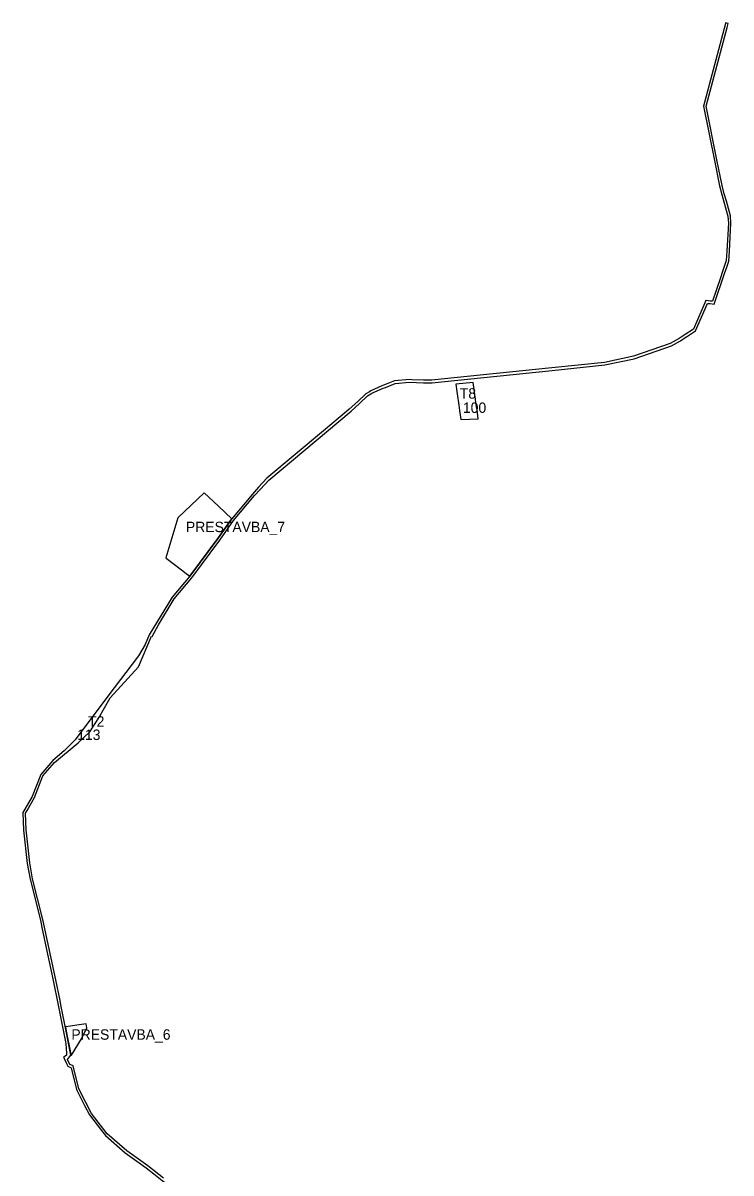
# Model space of a CAD drawing. Extents: x -477001 to -465642, y -1158278 to -1150672.
# Drawn here: x -473383 to -472568, y -1152921 to -1151597 of the extents above; entities that cross this region are included whole.
import ezdxf

# ---------------------------------------------------------------- set-up
doc = ezdxf.new("R2010")
doc.units = 0
for name, color, linetype in [('prestavba_n', 7, 'Continuous'), ('VPS_id', 7, 'Continuous'), ('VPS_n', 7, 'Continuous'), ('vyvlastneni_n', 7, 'Continuous')]:
    doc.layers.add(name, color=color, linetype=linetype)

msp = doc.modelspace()

# ---------------------------------------------------------------- linework, layer by layer
at = {"layer": 'prestavba_n'}
for p, q in [((-473174.2, -1152138.1), (-473204.5, -1152166.9)), ((-473157.8, -1152153.7), (-473174.2, -1152138.1)), ((-473142.5, -1152168.2), (-473157.8, -1152153.7)), ((-473204.5, -1152166.9), (-473218.5, -1152213)), ((-473142.7, -1152168.4), (-473142.5, -1152168.2)), ((-473218.5, -1152213), (-473218, -1152213.4)), ((-473218, -1152213.4), (-473198.9, -1152228.1)), ((-473198.9, -1152228.1), (-473196.5, -1152230)), ((-473196.5, -1152230), (-473190.8, -1152234.3)), ((-473190.8, -1152234.3), (-473190.8, -1152234.3)), ((-473328.1, -1152752.4), (-473334, -1152753.3)), ((-473320.9, -1152751.3), (-473328.1, -1152752.4)), ((-473327.1, -1152785.7), (-473315.4, -1152766.9)), ((-473327.6, -1152786), (-473327.1, -1152785.7))]:
    msp.add_line(p, q, dxfattribs=at)
for points in [[(-473190.8, -1152234.3), (-473158.4, -1152191), (-473142.7, -1152168.4)], [(-473315.4, -1152766.9), (-473309.3, -1152754.5), (-473310.2, -1152749.7), (-473320.9, -1152751.3)], [(-473334, -1152753.3), (-473333.1, -1152758.2), (-473328.2, -1152782.7)], [(-473328.2, -1152782.7), (-473327.6, -1152785.9), (-473327.6, -1152786)]]:
    msp.add_lwpolyline(points, dxfattribs=at)
at = {"layer": 'VPS_n'}
for p, q in [((-472570.1, -1151871.4), (-472569.6, -1151860.1)), ((-472611, -1151949.6), (-472620.5, -1151956)), ((-472618.8, -1151958.6), (-472608.6, -1151951.6)), ((-472984, -1152021.8), (-472987.9, -1152024.2)), ((-472864.4, -1152011.3), (-472884.3, -1152013.1)), ((-472884.3, -1152013.1), (-472883.2, -1152021.4)), ((-472883.2, -1152021.4), (-472882.8, -1152024.3)), ((-472861.8, -1152030.3), (-472864.4, -1152011.3)), ((-472997.3, -1152033), (-473007.1, -1152041.9)), ((-472987.9, -1152024.2), (-472997.3, -1152033)), ((-472882.8, -1152024.3), (-472881, -1152037.3)), ((-472861.3, -1152034.1), (-472861.8, -1152030.3)), ((-472860.5, -1152039.4), (-472861.3, -1152034.1)), ((-473010.4, -1152044.6), (-473036.8, -1152066.7)), ((-473007.1, -1152041.9), (-473010.4, -1152044.6)), ((-472881, -1152037.3), (-472880.1, -1152043.5)), ((-472880.1, -1152043.5), (-472878.7, -1152053.8)), ((-472860.1, -1152042.6), (-472860.5, -1152039.4)), ((-472858.7, -1152053), (-472860.1, -1152042.6)), ((-472878.7, -1152053.8), (-472858.7, -1152053)), ((-473036.8, -1152066.7), (-473101.9, -1152121.3)), ((-473226.7, -1152290.4), (-473208.7, -1152260.3)), ((-473234.1, -1152303.8), (-473226.7, -1152290.4)), ((-473242.1, -1152312.9), (-473249.8, -1152325.8)), ((-473234.8, -1152303.3), (-473234.1, -1152303.8)), ((-473345.1, -1152699.2), (-473359.8, -1152629.6)), ((-473354.5, -1152669.5), (-473350.8, -1152687.1)), ((-473340.1, -1152722.9), (-473345.1, -1152699.2)), ((-473342.1, -1152728.3), (-473333.7, -1152770.6)), ((-473335.4, -1152789.6), (-473332.7, -1152795.2)), ((-473325.6, -1152797.8), (-473328.7, -1152796.4)), ((-473327.5, -1152800.3), (-473327.1, -1152802)), ((-473292.3, -1152872.6), (-473287.9, -1152878.3)), ((-473287.9, -1152878.3), (-473265.1, -1152898.3)), ((-473265.1, -1152898.3), (-473240.9, -1152915.6))]:
    msp.add_line(p, q, dxfattribs=at)
for points in [[(-472596.2, -1151693.1), (-472572.2, -1151602.6), (-472571, -1151598), (-472573.9, -1151597.2), (-472574.1, -1151597.9), (-472599.3, -1151693), (-472586.8, -1151755.4)], [(-472583.9, -1151754.8), (-472583.9, -1151754.8), (-472596.2, -1151693.1)], [(-472586.8, -1151755.4), (-472580.8, -1151784.8), (-472578.3, -1151794.6), (-472575.8, -1151803.2), (-472571.3, -1151819.8), (-472570.7, -1151827.9), (-472572.5, -1151859.9), (-472573.1, -1151870.9)], [(-472569.6, -1151860.1), (-472567.7, -1151827.9), (-472568.4, -1151819.3), (-472572.9, -1151802.4), (-472575.4, -1151793.8), (-472577.8, -1151784.2), (-472583.9, -1151754.8)], [(-472573.1, -1151870.9), (-472577.3, -1151883.3), (-472579.9, -1151890.7), (-472589.1, -1151917.7), (-472591.5, -1151917.4), (-472594.1, -1151917.1), (-472596.3, -1151916.9), (-472596.8, -1151916.8), (-472611, -1151949.6)], [(-472608.6, -1151951.6), (-472594.9, -1151920.1), (-472594.1, -1151920.1), (-472591.5, -1151920.4), (-472587.1, -1151920.9), (-472574.6, -1151884.5), (-472572.9, -1151879.6), (-472570.1, -1151871.4)], [(-472620.5, -1151956), (-472627.4, -1151960.7), (-472637.6, -1151966.4)], [(-472637.6, -1151966.4), (-472680, -1151980.9), (-472713.3, -1151988), (-472774.1, -1151994.2)], [(-472773.7, -1151997.2), (-472712.8, -1151991), (-472679.2, -1151983.8), (-472636.3, -1151969.1)], [(-472636.3, -1151969.1), (-472625.9, -1151963.3), (-472619.2, -1151958.8), (-472618.8, -1151958.6)], [(-472774.1, -1151994.2), (-472901.3, -1152007.4), (-472912, -1152008.4), (-472913.7, -1152008.4), (-472921.6, -1152008.6), (-472935.2, -1152008), (-472937.8, -1152007.9), (-472955.2, -1152009.3), (-472964.7, -1152013.2), (-472967.7, -1152014.4), (-472969.5, -1152015.2), (-472982.5, -1152020.8), (-472984, -1152021.8)], [(-473005.1, -1152044.1), (-472995.3, -1152035.2), (-472986.1, -1152026.6), (-472982.4, -1152024.3), (-472981.1, -1152023.5), (-472968.3, -1152017.9), (-472966.5, -1152017.2), (-472963.6, -1152016), (-472954.5, -1152012.2), (-472937.7, -1152010.9), (-472921.7, -1152011.6), (-472913.6, -1152011.4), (-472911.9, -1152011.4), (-472901, -1152010.4), (-472773.7, -1151997.2)], [(-473140.4, -1152170.2), (-473116.1, -1152141.5), (-473109.4, -1152133.9), (-473099.8, -1152123.5), (-473005.1, -1152044.1)], [(-473101.9, -1152121.3), (-473111.7, -1152131.9), (-473118.4, -1152139.6), (-473142.7, -1152168.4)], [(-473142.7, -1152168.4), (-473158.4, -1152191), (-473190.8, -1152234.3), (-473211.1, -1152258.5), (-473237.4, -1152301.9), (-473242.1, -1152312.9)], [(-473208.7, -1152260.3), (-473188.4, -1152236.2), (-473156, -1152192.7), (-473140.4, -1152170.2)], [(-473359.8, -1152629.6), (-473371.7, -1152582.6), (-473375.1, -1152564.4), (-473379.3, -1152526.4), (-473379.8, -1152507.3), (-473377.9, -1152504.2), (-473369.4, -1152489.1), (-473359.8, -1152464.1), (-473346.4, -1152448.6), (-473319.2, -1152426), (-473305.7, -1152413.3), (-473295.5, -1152397.2), (-473282.6, -1152374.3), (-473249.7, -1152338.7), (-473234.8, -1152303.3)], [(-473249.8, -1152325.8), (-473285, -1152372.5), (-473322.9, -1152422.7), (-473335.3, -1152435.5)], [(-473335.3, -1152435.5), (-473348.5, -1152446.4), (-473362.4, -1152462.5), (-473372.1, -1152487.9), (-473380.5, -1152502.7), (-473382.8, -1152506.5), (-473382.3, -1152526.6), (-473378.1, -1152564.9), (-473374.7, -1152583.3), (-473362.7, -1152630.4)], [(-473362.7, -1152630.4), (-473361, -1152638.7), (-473354.5, -1152669.5)], [(-473350.8, -1152687.1), (-473348.1, -1152699.8), (-473342.1, -1152728.3)], [(-473331.6, -1152790.6), (-473328, -1152786.3), (-473327.6, -1152786), (-473327.6, -1152785.9), (-473333.1, -1152758.2), (-473339.1, -1152727.7), (-473340.1, -1152722.9)], [(-473333.7, -1152770.6), (-473333.5, -1152772.9), (-473332.7, -1152783.5)], [(-473332.7, -1152783.5), (-473332.6, -1152785.9), (-473335.7, -1152788), (-473336.1, -1152788.3), (-473335.9, -1152788.6), (-473335.4, -1152789.6)], [(-473328.7, -1152796.4), (-473328.8, -1152796.2), (-473331, -1152791.8), (-473331.6, -1152790.6)], [(-473332.7, -1152795.2), (-473331, -1152798.6), (-473327.5, -1152800.3)], [(-473327.1, -1152802), (-473321.3, -1152825.4), (-473311.9, -1152843.8)], [(-473310.3, -1152840.2), (-473318.5, -1152824.4), (-473324.9, -1152798.2), (-473325.3, -1152798), (-473325.6, -1152797.8)], [(-473311.9, -1152843.8), (-473306.4, -1152854.4), (-473292.3, -1152872.6)], [(-473285.7, -1152876.3), (-473303.9, -1152852.8), (-473310.3, -1152840.2)], [(-473221, -1152927.4), (-473239.1, -1152913.2), (-473263.2, -1152896), (-473285.7, -1152876.3)], [(-473240.9, -1152915.6), (-473232, -1152922.5), (-473222.5, -1152930), (-473216.1, -1152934.6), (-473205.2, -1152943.6), (-473202.5, -1152946.4)]]:
    msp.add_lwpolyline(points, dxfattribs=at)
at = {"layer": 'vyvlastneni_n'}
for p, q in [((-472570.1, -1151871.4), (-472569.6, -1151860.1)), ((-472611, -1151949.6), (-472620.5, -1151956)), ((-472618.8, -1151958.6), (-472608.6, -1151951.6)), ((-472984, -1152021.8), (-472987.9, -1152024.2)), ((-472864.4, -1152011.3), (-472884.3, -1152013.1)), ((-472884.3, -1152013.1), (-472883.2, -1152021.4)), ((-472883.2, -1152021.4), (-472882.8, -1152024.3)), ((-472861.8, -1152030.3), (-472864.4, -1152011.3)), ((-472997.3, -1152033), (-473007.1, -1152041.9)), ((-472987.9, -1152024.2), (-472997.3, -1152033)), ((-472882.8, -1152024.3), (-472881, -1152037.3)), ((-472861.3, -1152034.1), (-472861.8, -1152030.3)), ((-472860.5, -1152039.4), (-472861.3, -1152034.1)), ((-473010.4, -1152044.6), (-473036.8, -1152066.7)), ((-473007.1, -1152041.9), (-473010.4, -1152044.6)), ((-472881, -1152037.3), (-472880.1, -1152043.5)), ((-472880.1, -1152043.5), (-472878.7, -1152053.8)), ((-472860.1, -1152042.6), (-472860.5, -1152039.4)), ((-472858.7, -1152053), (-472860.1, -1152042.6)), ((-472878.7, -1152053.8), (-472858.7, -1152053)), ((-473036.8, -1152066.7), (-473101.9, -1152121.3)), ((-473226.7, -1152290.4), (-473208.7, -1152260.3)), ((-473234.1, -1152303.8), (-473226.7, -1152290.4)), ((-473242.1, -1152312.9), (-473249.8, -1152325.8)), ((-473234.8, -1152303.3), (-473234.1, -1152303.8)), ((-473345.1, -1152699.2), (-473359.8, -1152629.6)), ((-473354.5, -1152669.5), (-473350.8, -1152687.1)), ((-473340.1, -1152722.9), (-473345.1, -1152699.2)), ((-473342.1, -1152728.3), (-473333.7, -1152770.6)), ((-473335.4, -1152789.6), (-473332.7, -1152795.2)), ((-473325.6, -1152797.8), (-473328.7, -1152796.4)), ((-473327.5, -1152800.3), (-473327.1, -1152802)), ((-473292.3, -1152872.6), (-473287.9, -1152878.3)), ((-473287.9, -1152878.3), (-473265.1, -1152898.3)), ((-473265.1, -1152898.3), (-473240.9, -1152915.6))]:
    msp.add_line(p, q, dxfattribs=at)
for points in [[(-472596.2, -1151693.1), (-472572.2, -1151602.6), (-472571, -1151598), (-472573.9, -1151597.2), (-472574.1, -1151597.9), (-472599.3, -1151693), (-472586.8, -1151755.4)], [(-472583.9, -1151754.8), (-472583.9, -1151754.8), (-472596.2, -1151693.1)], [(-472586.8, -1151755.4), (-472580.8, -1151784.8), (-472578.3, -1151794.6), (-472575.8, -1151803.2), (-472571.3, -1151819.8), (-472570.7, -1151827.9), (-472572.5, -1151859.9), (-472573.1, -1151870.9)], [(-472569.6, -1151860.1), (-472567.7, -1151827.9), (-472568.4, -1151819.3), (-472572.9, -1151802.4), (-472575.4, -1151793.8), (-472577.8, -1151784.2), (-472583.9, -1151754.8)], [(-472573.1, -1151870.9), (-472577.3, -1151883.3), (-472579.9, -1151890.7), (-472589.1, -1151917.7), (-472591.5, -1151917.4), (-472594.1, -1151917.1), (-472596.3, -1151916.9), (-472596.8, -1151916.8), (-472611, -1151949.6)], [(-472608.6, -1151951.6), (-472594.9, -1151920.1), (-472594.1, -1151920.1), (-472591.5, -1151920.4), (-472587.1, -1151920.9), (-472574.6, -1151884.5), (-472572.9, -1151879.6), (-472570.1, -1151871.4)], [(-472620.5, -1151956), (-472627.4, -1151960.7), (-472637.6, -1151966.4)], [(-472637.6, -1151966.4), (-472680, -1151980.9), (-472713.3, -1151988), (-472774.1, -1151994.2)], [(-472773.7, -1151997.2), (-472712.8, -1151991), (-472679.2, -1151983.8), (-472636.3, -1151969.1)], [(-472636.3, -1151969.1), (-472625.9, -1151963.3), (-472619.2, -1151958.8), (-472618.8, -1151958.6)], [(-472774.1, -1151994.2), (-472901.3, -1152007.4), (-472912, -1152008.4), (-472913.7, -1152008.4), (-472921.6, -1152008.6), (-472935.2, -1152008), (-472937.8, -1152007.9), (-472955.2, -1152009.3), (-472964.7, -1152013.2), (-472967.7, -1152014.4), (-472969.5, -1152015.2), (-472982.5, -1152020.8), (-472984, -1152021.8)], [(-473005.1, -1152044.1), (-472995.3, -1152035.2), (-472986.1, -1152026.6), (-472982.4, -1152024.3), (-472981.1, -1152023.5), (-472968.3, -1152017.9), (-472966.5, -1152017.2), (-472963.6, -1152016), (-472954.5, -1152012.2), (-472937.7, -1152010.9), (-472921.7, -1152011.6), (-472913.6, -1152011.4), (-472911.9, -1152011.4), (-472901, -1152010.4), (-472773.7, -1151997.2)], [(-473140.4, -1152170.2), (-473116.1, -1152141.5), (-473109.4, -1152133.9), (-473099.8, -1152123.5), (-473005.1, -1152044.1)], [(-473101.9, -1152121.3), (-473111.7, -1152131.9), (-473118.4, -1152139.6), (-473142.7, -1152168.4)], [(-473142.7, -1152168.4), (-473158.4, -1152191), (-473190.8, -1152234.3), (-473211.1, -1152258.5), (-473237.4, -1152301.9), (-473242.1, -1152312.9)], [(-473208.7, -1152260.3), (-473188.4, -1152236.2), (-473156, -1152192.7), (-473140.4, -1152170.2)], [(-473359.8, -1152629.6), (-473371.7, -1152582.6), (-473375.1, -1152564.4), (-473379.3, -1152526.4), (-473379.8, -1152507.3), (-473377.9, -1152504.2), (-473369.4, -1152489.1), (-473359.8, -1152464.1), (-473346.4, -1152448.6), (-473319.2, -1152426), (-473305.7, -1152413.3), (-473295.5, -1152397.2), (-473282.6, -1152374.3), (-473249.7, -1152338.7), (-473234.8, -1152303.3)], [(-473249.8, -1152325.8), (-473285, -1152372.5), (-473322.9, -1152422.7), (-473335.3, -1152435.5)], [(-473335.3, -1152435.5), (-473348.5, -1152446.4), (-473362.4, -1152462.5), (-473372.1, -1152487.9), (-473380.5, -1152502.7), (-473382.8, -1152506.5), (-473382.3, -1152526.6), (-473378.1, -1152564.9), (-473374.7, -1152583.3), (-473362.7, -1152630.4)], [(-473362.7, -1152630.4), (-473361, -1152638.7), (-473354.5, -1152669.5)], [(-473350.8, -1152687.1), (-473348.1, -1152699.8), (-473342.1, -1152728.3)], [(-473331.6, -1152790.6), (-473328, -1152786.3), (-473327.6, -1152786), (-473327.6, -1152785.9), (-473333.1, -1152758.2), (-473339.1, -1152727.7), (-473340.1, -1152722.9)], [(-473333.7, -1152770.6), (-473333.5, -1152772.9), (-473332.7, -1152783.5)], [(-473332.7, -1152783.5), (-473332.6, -1152785.9), (-473335.7, -1152788), (-473336.1, -1152788.3), (-473335.9, -1152788.6), (-473335.4, -1152789.6)], [(-473328.7, -1152796.4), (-473328.8, -1152796.2), (-473331, -1152791.8), (-473331.6, -1152790.6)], [(-473332.7, -1152795.2), (-473331, -1152798.6), (-473327.5, -1152800.3)], [(-473327.1, -1152802), (-473321.3, -1152825.4), (-473311.9, -1152843.8)], [(-473310.3, -1152840.2), (-473318.5, -1152824.4), (-473324.9, -1152798.2), (-473325.3, -1152798), (-473325.6, -1152797.8)], [(-473311.9, -1152843.8), (-473306.4, -1152854.4), (-473292.3, -1152872.6)], [(-473285.7, -1152876.3), (-473303.9, -1152852.8), (-473310.3, -1152840.2)], [(-473221, -1152927.4), (-473239.1, -1152913.2), (-473263.2, -1152896), (-473285.7, -1152876.3)], [(-473240.9, -1152915.6), (-473232, -1152922.5), (-473222.5, -1152930), (-473216.1, -1152934.6), (-473205.2, -1152943.6), (-473202.5, -1152946.4)]]:
    msp.add_lwpolyline(points, dxfattribs=at)

# ---------------------------------------------------------------- texts
at = {"layer": 'prestavba_n'}
for s, p in [('PRESTAVBA_7', (-473195.2, -1152183.5)), ('PRESTAVBA_6', (-473327.1, -1152768))]:
    msp.add_text(s, height=12, dxfattribs=at).set_placement(p)
at = {"layer": 'VPS_id'}
for s, p in [('100', (-472876.3, -1152046.2)), ('113', (-473320.4, -1152422.8))]:
    msp.add_text(s, height=12, dxfattribs=at).set_placement(p)
at = {"layer": 'VPS_n'}
for s, p in [('T8', (-472879.9, -1152029.8)), ('T2', (-473307.8, -1152407.5))]:
    msp.add_text(s, height=12, dxfattribs=at).set_placement(p)

doc.saveas('drawing.dxf')
